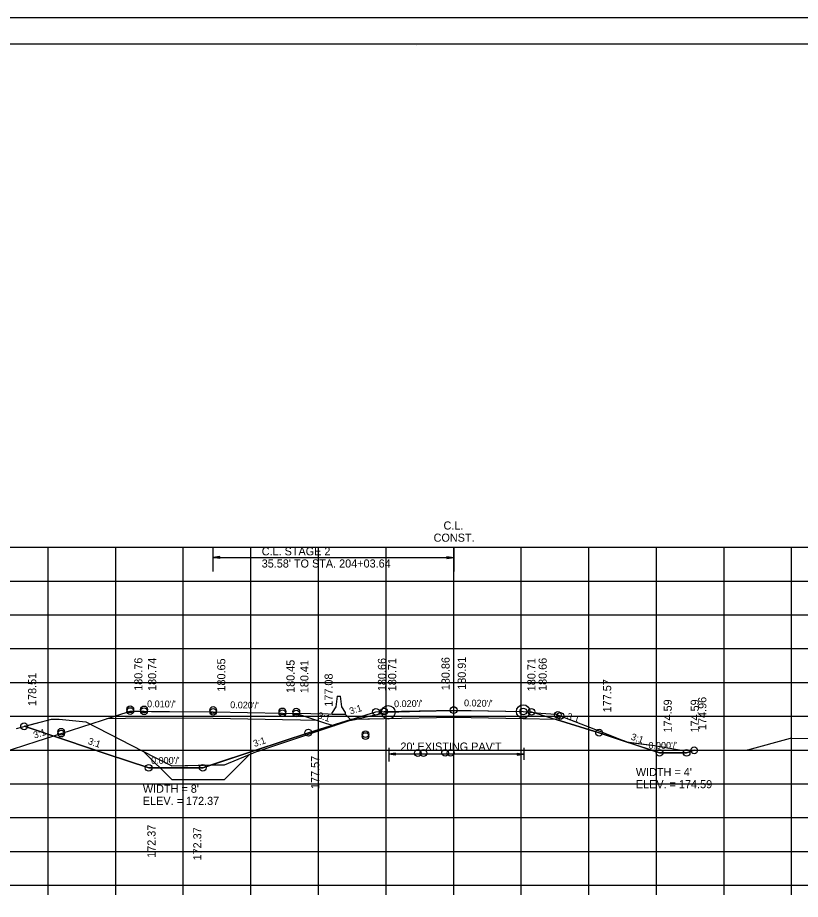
# Model space of a CAD drawing. Extents: x 1372132 to 1372465, y 380083 to 381790.
# Drawn here: x 1372237.5 to 1372353.3, y 380593.1 to 380723.5 of the extents above; entities that cross this region are included whole.
import ezdxf

# ---------------------------------------------------------------- set-up
doc = ezdxf.new("R2010")
doc.units = 0
for name, color, linetype in [('R_Alt Surface', 7, 'Continuous'), ('R_Axis', 7, 'Continuous'), ('R_Border', 7, 'Continuous'), ('R_Dimension', 7, 'Continuous'), ('R_Draft', 7, 'Continuous'), ('R_Erosion', 7, 'Continuous'), ('R_Exist Surface', 7, 'Continuous'), ('R_Fin Surface', 7, 'Continuous'), ('R_Grid', 7, 'Continuous'), ('R_No Plot', 7, 'Continuous'), ('R_Xsect Elev', 7, 'Continuous'), ('R_Xsect Slope', 7, 'Continuous')]:
    doc.layers.add(name, color=color, linetype=linetype)

msp = doc.modelspace()

# ---------------------------------------------------------------- linework, layer by layer
at = {"layer": 'R_Alt Surface'}
for points in [[(1372281.99, 380619.5), (1372276.67, 380619.6), (1372266.43, 380619.8), (1372256.2, 380619.89), (1372250.71, 380619.79)], [(1372317.19, 380619.67), (1372312.31, 380619.77), (1372302.01, 380619.98), (1372291.71, 380619.77), (1372286.83, 380619.67)]]:
    msp.add_lwpolyline(points, dxfattribs=at)
at = {"layer": 'R_Axis'}
for p, q in [((1372162.01, 380595.15), (1372442.01, 380595.15)), ((1372242.01, 380593.75), (1372242.01, 380595.15)), ((1372252.01, 380593.75), (1372252.01, 380595.15)), ((1372262.01, 380593.75), (1372262.01, 380595.15)), ((1372272.01, 380593.75), (1372272.01, 380595.15)), ((1372282.01, 380593.75), (1372282.01, 380595.15)), ((1372292.01, 380593.75), (1372292.01, 380595.15)), ((1372302.01, 380593.75), (1372302.01, 380595.15)), ((1372312.01, 380593.75), (1372312.01, 380595.15)), ((1372322.01, 380593.75), (1372322.01, 380595.15)), ((1372332.01, 380593.75), (1372332.01, 380595.15)), ((1372342.01, 380593.75), (1372342.01, 380595.15)), ((1372352.01, 380593.75), (1372352.01, 380595.15))]:
    msp.add_line(p, q, dxfattribs=at)
at = {"layer": 'R_Border'}
for p, q in [((1372144.01, 380719.61), (1372460.19, 380719.61)), ((1372296.53, 380719.35), (1372296.53, 380719.35)), ((1372296.53, 380719.35), (1372296.53, 380719.35))]:
    msp.add_line(p, q, dxfattribs=at)
at = {"layer": 'R_Draft'}
for p, q in [((1372266.43, 380641.55), (1372266.43, 380645.15)), ((1372302.01, 380645.15), (1372302.01, 380641.55)), ((1372267.43, 380643.79), (1372266.43, 380643.64)), ((1372267.43, 380643.79), (1372266.43, 380643.64)), ((1372266.43, 380643.64), (1372302.01, 380643.64)), ((1372267.43, 380643.49), (1372266.43, 380643.64)), ((1372267.43, 380643.49), (1372266.43, 380643.64)), ((1372267.43, 380643.76), (1372266.6, 380643.64)), ((1372267.43, 380643.76), (1372266.6, 380643.64)), ((1372267.43, 380643.51), (1372266.6, 380643.64)), ((1372267.43, 380643.51), (1372266.6, 380643.64)), ((1372267.43, 380643.74), (1372266.77, 380643.64)), ((1372267.43, 380643.74), (1372266.77, 380643.64)), ((1372267.43, 380643.54), (1372266.77, 380643.64)), ((1372267.43, 380643.54), (1372266.77, 380643.64)), ((1372267.43, 380643.71), (1372266.94, 380643.64)), ((1372267.43, 380643.71), (1372266.94, 380643.64)), ((1372267.43, 380643.56), (1372266.94, 380643.64)), ((1372267.43, 380643.56), (1372266.94, 380643.64)), ((1372267.43, 380643.69), (1372267.11, 380643.64)), ((1372267.43, 380643.69), (1372267.11, 380643.64)), ((1372267.43, 380643.59), (1372267.11, 380643.64)), ((1372267.43, 380643.59), (1372267.11, 380643.64)), ((1372267.43, 380643.66), (1372267.28, 380643.64)), ((1372267.43, 380643.66), (1372267.28, 380643.64)), ((1372267.43, 380643.61), (1372267.28, 380643.64)), ((1372267.43, 380643.61), (1372267.28, 380643.64)), ((1372267.43, 380643.49), (1372267.43, 380643.79)), ((1372267.43, 380643.49), (1372267.43, 380643.79)), ((1372301.01, 380643.79), (1372302.01, 380643.64)), ((1372301.01, 380643.79), (1372301.01, 380643.49)), ((1372301.01, 380643.79), (1372302.01, 380643.64)), ((1372301.01, 380643.79), (1372301.01, 380643.49)), ((1372301.01, 380643.76), (1372301.85, 380643.64)), ((1372301.01, 380643.76), (1372301.85, 380643.64)), ((1372301.01, 380643.74), (1372301.68, 380643.64)), ((1372301.01, 380643.74), (1372301.68, 380643.64)), ((1372301.01, 380643.71), (1372301.51, 380643.64)), ((1372301.01, 380643.71), (1372301.51, 380643.64)), ((1372301.01, 380643.69), (1372301.34, 380643.64)), ((1372301.01, 380643.69), (1372301.34, 380643.64)), ((1372301.01, 380643.66), (1372301.17, 380643.64)), ((1372301.01, 380643.66), (1372301.17, 380643.64)), ((1372301.01, 380643.49), (1372302.01, 380643.64)), ((1372301.01, 380643.59), (1372301.34, 380643.64)), ((1372301.01, 380643.54), (1372301.68, 380643.64)), ((1372301.01, 380643.51), (1372301.85, 380643.64)), ((1372301.01, 380643.56), (1372301.51, 380643.64)), ((1372301.01, 380643.61), (1372301.17, 380643.64)), ((1372301.01, 380643.49), (1372302.01, 380643.64)), ((1372301.01, 380643.59), (1372301.34, 380643.64)), ((1372301.01, 380643.54), (1372301.68, 380643.64)), ((1372301.01, 380643.51), (1372301.85, 380643.64)), ((1372301.01, 380643.56), (1372301.51, 380643.64)), ((1372301.01, 380643.61), (1372301.17, 380643.64)), ((1372284.76, 380623.11), (1372284.59, 380621.53)), ((1372284.76, 380623.11), (1372285.26, 380623.11)), ((1372285.44, 380621.53), (1372285.26, 380623.11)), ((1372284.59, 380621.53), (1372284.01, 380620.7)), ((1372284.01, 380620.45), (1372284.01, 380620.7)), ((1372286.01, 380620.7), (1372285.44, 380621.53)), ((1372286.01, 380620.45), (1372286.01, 380620.7)), ((1372284.01, 380620.45), (1372286.01, 380620.45)), ((1372292.42, 380615.47), (1372292.42, 380613.45)), ((1372312.4, 380615.47), (1372312.4, 380613.69)), ((1372293.42, 380614.7), (1372292.42, 380614.55)), ((1372293.42, 380614.7), (1372292.42, 380614.55)), ((1372312.4, 380614.55), (1372292.42, 380614.55)), ((1372293.42, 380614.4), (1372292.42, 380614.55)), ((1372293.42, 380614.4), (1372292.42, 380614.55)), ((1372293.42, 380614.67), (1372292.59, 380614.55)), ((1372293.42, 380614.67), (1372292.59, 380614.55)), ((1372293.42, 380614.42), (1372292.59, 380614.55)), ((1372293.42, 380614.42), (1372292.59, 380614.55)), ((1372293.42, 380614.65), (1372292.76, 380614.55)), ((1372293.42, 380614.65), (1372292.76, 380614.55)), ((1372293.42, 380614.45), (1372292.76, 380614.55)), ((1372293.42, 380614.45), (1372292.76, 380614.55)), ((1372293.42, 380614.62), (1372292.93, 380614.55)), ((1372293.42, 380614.62), (1372292.93, 380614.55)), ((1372293.42, 380614.47), (1372292.93, 380614.55)), ((1372293.42, 380614.47), (1372292.93, 380614.55)), ((1372293.42, 380614.6), (1372293.1, 380614.55)), ((1372293.42, 380614.6), (1372293.1, 380614.55)), ((1372293.42, 380614.5), (1372293.1, 380614.55)), ((1372293.42, 380614.5), (1372293.1, 380614.55)), ((1372293.42, 380614.57), (1372293.27, 380614.55)), ((1372293.42, 380614.57), (1372293.27, 380614.55)), ((1372293.42, 380614.52), (1372293.27, 380614.55)), ((1372293.42, 380614.52), (1372293.27, 380614.55)), ((1372293.42, 380614.4), (1372293.42, 380614.7)), ((1372293.42, 380614.4), (1372293.42, 380614.7)), ((1372311.4, 380614.7), (1372312.4, 380614.55)), ((1372311.4, 380614.7), (1372311.4, 380614.4)), ((1372311.4, 380614.67), (1372312.24, 380614.55)), ((1372311.4, 380614.65), (1372312.07, 380614.55)), ((1372311.4, 380614.62), (1372311.9, 380614.55)), ((1372311.4, 380614.6), (1372311.73, 380614.55)), ((1372311.4, 380614.57), (1372311.56, 380614.55)), ((1372311.4, 380614.4), (1372312.4, 380614.55)), ((1372311.4, 380614.5), (1372311.73, 380614.55)), ((1372311.4, 380614.45), (1372312.07, 380614.55)), ((1372311.4, 380614.42), (1372312.24, 380614.55)), ((1372311.4, 380614.47), (1372311.9, 380614.55)), ((1372311.4, 380614.52), (1372311.56, 380614.55)), ((1372292.42, 380613.69), (1372292.42, 380613.69))]:
    msp.add_line(p, q, dxfattribs=at)
at = {"layer": 'R_Erosion'}
for p, q in [((1372286.01, 380620.42), (1372278.29, 380620.57)), ((1372286.01, 380620.42), (1372286.84, 380619.59)), ((1372260.29, 380610.81), (1372256.19, 380614.91)), ((1372268.1, 380610.81), (1372271.75, 380614.46)), ((1372260.29, 380610.81), (1372268.1, 380610.81))]:
    msp.add_line(p, q, dxfattribs=at)
at = {"layer": 'R_Exist Surface'}
msp.add_lwpolyline([(1372237.31, 380618.36), (1372242.52, 380619.74), (1372243.66, 380619.71), (1372247.57, 380619.33), (1372257.77, 380614.1), (1372260.3, 380612.8), (1372267.36, 380612.97), (1372268.1, 380612.97), (1372272.97, 380614.96), (1372273.1, 380615), (1372273.92, 380615.26), (1372286.59, 380619.5), (1372289.47, 380620.14), (1372292.33, 380620.74), (1372297.03, 380620.88), (1372301.86, 380621.01), (1372307.07, 380620.93), (1372312.29, 380620.86), (1372314.91, 380620.63), (1372317.13, 380620.46), (1372323.65, 380617.92), (1372327.59, 380616.35), (1372331.73, 380615.83), (1372335.96, 380615.1), (1372345.44, 380615.18), (1372345.46, 380615.18), (1372345.53, 380615.2), (1372351.82, 380616.91), (1372361.74, 380616.87)], dxfattribs=at)
at = {"layer": 'R_Fin Surface'}
for points in [[(1372234.91, 380614.67), (1372240.37, 380616.44), (1372243.94, 380617.59), (1372250.06, 380619.58), (1372254.16, 380620.91), (1372254.61, 380620.9), (1372256.2, 380620.89), (1372257.33, 380620.87), (1372259.95, 380620.85), (1372266.43, 380620.8), (1372271.49, 380620.7), (1372276.67, 380620.6), (1372278.29, 380620.57), (1372278.72, 380620.56), (1372280.1, 380620.11), (1372283.05, 380619.15), (1372284.37, 380618.72)], [(1372238.46, 380618.66), (1372244.63, 380616.6), (1372247.69, 380615.58), (1372250.77, 380614.56), (1372256.89, 380612.52), (1372264.89, 380612.52), (1372272.73, 380615.13), (1372280.51, 380617.72), (1372286.83, 380619.67), (1372290.51, 380620.81), (1372291.71, 380620.85), (1372302.01, 380621.06), (1372312.31, 380620.85), (1372313.52, 380620.81), (1372317.19, 380619.67), (1372323.52, 380617.72), (1372332.47, 380614.74), (1372336.47, 380614.74), (1372337.59, 380615.11)]]:
    msp.add_lwpolyline(points, dxfattribs=at)
at = {"layer": 'R_Grid'}
for p, q in [((1372162.01, 380645.15), (1372442.01, 380645.15)), ((1372242.01, 380595.15), (1372242.01, 380645.15)), ((1372252.01, 380595.15), (1372252.01, 380645.15)), ((1372262.01, 380595.15), (1372262.01, 380645.15)), ((1372272.01, 380595.15), (1372272.01, 380645.15)), ((1372282.01, 380595.15), (1372282.01, 380645.15)), ((1372292.01, 380595.15), (1372292.01, 380645.15)), ((1372302.01, 380595.15), (1372302.01, 380645.15)), ((1372312.01, 380595.15), (1372312.01, 380645.15)), ((1372322.01, 380595.15), (1372322.01, 380645.15)), ((1372332.01, 380595.15), (1372332.01, 380645.15)), ((1372342.01, 380595.15), (1372342.01, 380645.15)), ((1372352.01, 380595.15), (1372352.01, 380645.15)), ((1372162.01, 380640.15), (1372442.01, 380640.15)), ((1372162.01, 380635.15), (1372442.01, 380635.15)), ((1372162.01, 380630.15), (1372442.01, 380630.15)), ((1372162.01, 380625.15), (1372442.01, 380625.15)), ((1372162.01, 380620.15), (1372442.01, 380620.15)), ((1372162.01, 380615.15), (1372442.01, 380615.15)), ((1372162.01, 380610.15), (1372442.01, 380610.15)), ((1372162.01, 380605.15), (1372442.01, 380605.15)), ((1372162.01, 380600.15), (1372442.01, 380600.15)), ((1372162.01, 380595.15), (1372442.01, 380595.15))]:
    msp.add_line(p, q, dxfattribs=at)
at = {"layer": 'R_No Plot'}
msp.add_line((1372131.61, 380723.5), (1372464.95, 380723.5), dxfattribs=at)
for points in [[(1372131.61, 380723.5), (1372464.95, 380723.5), (1372464.95, 380510.17), (1372131.61, 380510.17)], [(1372377.93, 380719.61), (1372377.93, 380709.73), (1372413.67, 380709.73), (1372413.67, 380706.81), (1372436.87, 380706.81), (1372436.87, 380682.48), (1372460.19, 380682.48), (1372460.19, 380514.15), (1372144.01, 380514.15), (1372144.01, 380719.61)], [(1372287.42, 380619.69), (1372289.47, 380620.14), (1372292.33, 380620.74), (1372297.03, 380620.88), (1372301.86, 380621.01), (1372307.07, 380620.93), (1372312.29, 380620.86), (1372314.91, 380620.63), (1372317.13, 380620.46), (1372323.65, 380617.92), (1372327.31, 380616.46), (1372323.52, 380617.72), (1372317.19, 380619.67), (1372312.31, 380619.77), (1372302.01, 380619.98), (1372291.71, 380619.77)], [(1372238.46, 380618.66), (1372242.52, 380619.74), (1372243.66, 380619.71), (1372247.57, 380619.33), (1372257.77, 380614.1), (1372260.3, 380612.8), (1372266.17, 380612.94), (1372264.89, 380612.52), (1372256.89, 380612.52), (1372250.77, 380614.56), (1372247.69, 380615.58), (1372244.63, 380616.6)], [(1372266.17, 380612.94), (1372267.36, 380612.97), (1372268.1, 380612.97), (1372272.97, 380614.96), (1372273.1, 380615), (1372273.92, 380615.26), (1372286.59, 380619.5), (1372287.42, 380619.69), (1372286.83, 380619.67), (1372280.51, 380617.72), (1372272.73, 380615.13)], [(1372327.31, 380616.46), (1372327.59, 380616.35), (1372327.68, 380616.34)], [(1372327.68, 380616.34), (1372331.73, 380615.83), (1372335.96, 380615.1), (1372337.59, 380615.11), (1372336.47, 380614.74), (1372332.47, 380614.74)]]:
    msp.add_lwpolyline(points, close=True, dxfattribs=at)
for centre, radius in [((1372254.16, 380621.18), 0.5), ((1372254.16, 380620.91), 0.5), ((1372256.2, 380621.16), 0.5), ((1372256.2, 380620.89), 0.5), ((1372266.43, 380621.07), 0.5), ((1372266.43, 380620.8), 0.5), ((1372276.67, 380620.87), 0.5), ((1372276.67, 380620.6), 0.5), ((1372278.72, 380620.83), 0.5), ((1372278.72, 380620.56), 0.5), ((1372290.51, 380620.81), 0.5), ((1372291.71, 380620.85), 0.5), ((1372292.33, 380620.74), 1), ((1372302.01, 380621.06), 0.5), ((1372312.29, 380620.86), 1), ((1372312.31, 380620.85), 0.5), ((1372313.52, 380620.81), 0.5), ((1372317.42, 380620.35), 0.5), ((1372317.79, 380620.2), 0.5), ((1372238.46, 380618.66), 0.5), ((1372243.94, 380617.86), 0.5), ((1372243.94, 380617.59), 0.5), ((1372280.51, 380617.72), 0.5), ((1372288.97, 380617.5), 0.5), ((1372323.52, 380617.72), 0.5), ((1372288.97, 380617.22), 0.5), ((1372337.59, 380615.11), 0.5), ((1372296.71, 380614.71), 0.5), ((1372297.53, 380614.71), 0.5), ((1372300.74, 380614.73), 0.5), ((1372301.56, 380614.74), 0.5), ((1372332.47, 380614.74), 0.5), ((1372336.47, 380614.74), 0.5), ((1372256.89, 380612.52), 0.5), ((1372264.89, 380612.52), 0.5)]:
    msp.add_circle(centre, radius, dxfattribs=at)
at = {"layer": 'R_Xsect Elev'}
msp.add_line((1372302.01, 380621), (1372302.01, 380631), dxfattribs=at)

# ---------------------------------------------------------------- texts
at = {"layer": 'R_Dimension'}
for s, p in [("WIDTH = 4'", (1372328.96, 380611.3)), ('ELEV. = 174.59', (1372328.96, 380609.5)), ("WIDTH = 8'", (1372256.03, 380608.83)), ('ELEV. = 172.37', (1372256.03, 380607.03))]:
    msp.add_text(s, height=1.2, dxfattribs=at).set_placement(p)
at = {"layer": 'R_Draft'}
for s, p in [('C.L. ', (1372300.51, 380647.77)), ('CONST. ', (1372299.04, 380645.97)), ('C.L. STAGE 2', (1372273.61, 380643.95)), ("35.58' TO STA. 204+03.64", (1372273.61, 380642.15)), ("20' EXISTING PAV'T", (1372294.13, 380615.06))]:
    msp.add_text(s, height=1.2, rotation=360, dxfattribs=at).set_placement(p)
at = {"layer": 'R_Xsect Elev'}
for s, p in [('180.76', (1372255.96, 380623.91)), ('180.74', (1372258, 380623.89)), ('180.65', (1372268.23, 380623.8)), ('180.45', (1372278.47, 380623.6)), ('180.66', (1372292, 380623.86)), ('180.71', (1372293.51, 380623.85)), ('180.86', (1372301.41, 380624)), ('180.91', (1372303.81, 380624.06)), ('180.71', (1372314.11, 380623.85)), ('180.66', (1372315.77, 380623.89)), ('180.41', (1372280.52, 380623.56)), ('178.51', (1372240.26, 380621.66)), ('177.08', (1372284.11, 380621.56)), ('177.57', (1372325.32, 380620.72)), ('174.59', (1372334.27, 380617.74)), ('174.59', (1372338.27, 380617.74)), ('174.96', (1372339.39, 380618.11)), ('177.57', (1372282.12, 380609.38)), ('172.37', (1372257.9, 380599.2)), ('172.37', (1372264.68, 380598.81))]:
    msp.add_text(s, height=1.2, rotation=90, dxfattribs=at).set_placement(p)
at = {"layer": 'R_Xsect Slope'}
for s, rotation, p in [("0.010'/'", 359.4942, (1372256.65, 380621.49)), ("0.020'/'", 358.8749, (1372268.94, 380621.35)), ("0.020'/'", 1.1458, (1372293.2, 380621.48)), ("0.020'/'", 358.8542, (1372303.53, 380621.63)), ('3:1', 341.9846, (1372281.79, 380619.87)), ('3:1', 17.1363, (1372286.75, 380620.4)), ('3:1', 342.8637, (1372318.67, 380619.74)), ('3:1', 17.9806, (1372240.01, 380616.84)), ('3:1', 341.5651, (1372247.83, 380616.06)), ('3:1', 18.4332, (1372272.54, 380615.59)), ('3:1', 341.5668, (1372328.15, 380616.71)), ("0.000'/'", 360, (1372330.82, 380615.34)), ("0.000'/'", 360, (1372257.24, 380613.12))]:
    msp.add_text(s, height=1, rotation=rotation, dxfattribs=at).set_placement(p)

doc.saveas('drawing.dxf')
